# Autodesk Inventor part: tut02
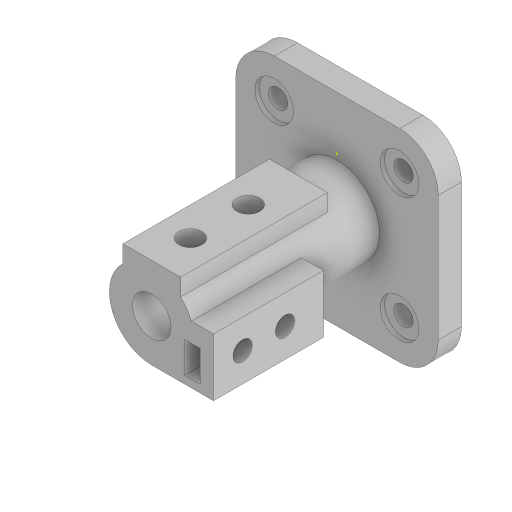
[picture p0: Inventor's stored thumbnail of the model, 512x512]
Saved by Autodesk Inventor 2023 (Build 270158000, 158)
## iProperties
Created: 2015-03
Part Number: tut02
Material: Generic
Document SubType Name: Modeling
Designer: Sandeep
Density: 1 g/cm^3
Appearance: Default
Author: Sandeep
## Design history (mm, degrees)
sketch "Sketch1"
  geometry: L1 (-32.5, -52.5)-(32.5, -52.5); L2 (52.5, -32.5)-(52.5, 32.5); L3 (32.5, 52.5)-(-32.5, 52.5); L4 (-52.5, 32.5)-(-52.5, -32.5); L5 (-52.5, -52.5)-(52.5, 52.5); L6 (52.5, -52.5)-(-52.5, 52.5); A1 r 20 centre (32.5, 32.5) between (52.5, 32.5) and (32.5, 52.5); A2 r 20 centre (32.5, -32.5) between (32.5, -52.5) and (52.5, -32.5); A3 r 20 centre (-32.5, -32.5) between (-52.5, -32.5) and (-32.5, -52.5); A4 r 20 centre (-32.5, 32.5) between (-32.5, 52.5) and (-52.5, 32.5); 1 further point
  constraints: 12 end point, 8 point on circle, 8 point on line, 8 tangent, 4 centre point, 2 equal radius, 2 midpoint, 2 parallel, 1 horizontal, 1 perpendicular
  dimensions: "d0" = 105 distance of L6.start L5.end; "d1" = 105 distance of L5.start L6.start; "d2" = 20 radius of A1; "d3" = 20 radius of A2
extrude "Extrusion1" new body sketch "Sketch1" distance "d4" = 12; taper "d5" = 0 deg
hole "Hole1" diameter "d8" = 10; stored, may be unused: countersink angle "d12" = 90 deg, drill point angle "d14" = 118 deg; dims "d9" = 6, "d10" = 20, "d11" = 2, "d13" = 8, "d15" = 10, "d16" = 10
hole "Hole2" diameter "d19" = 10; stored, may be unused: countersink angle "d23" = 90 deg, drill point angle "d25" = 118 deg; dims "d17" = 10, "d18" = 10, "d20" = 6, "d21" = 20, "d22" = 2, "d24" = 8
hole "Hole3" diameter "d28" = 10; stored, may be unused: countersink angle "d32" = 90 deg, drill point angle "d34" = 118 deg; dims "d26" = 10, "d27" = 10, "d29" = 6, "d30" = 20, "d31" = 2, "d33" = 8
hole "Hole4" diameter "d37" = 10; stored, may be unused: countersink angle "d41" = 90 deg, drill point angle "d43" = 118 deg; dims "d35" = 10, "d36" = 10, "d38" = 6, "d39" = 20, "d40" = 2, "d42" = 8
sketch "Sketch2"
  geometry: C1 r 22 at (0, 0); 1 further point
  constraints: 1 centre point, 1 coincident
  dimensions: "d44" = 44 diameter of C1
extrude "Extrusion2" join sketch "Sketch2" distance "d45" = 96; taper "d46" = 0 deg
sketch "Sketch3"
  geometry: L1 (-15, 16.093)-(-15, 25); L2 (15, 16.093)-(15, 25); L3 (-15, 25)-(15, 25); L4 (0, 0)-(20.619, 0); L5 (0, 6.043)-(0, 0); A1 r 22 centre (0, 0) between (15, 16.093) and (-15, 16.093); 1 further point
  constraints: 10 end point, 3 vertical, 2 horizontal, 2 point on circle, 1 centre point, 4 other
  dimensions: "d48" = 25 distance from line of point (0, 0) L3; "d49" = 30 distance of L1.end L2.end
extrude "Extrusion3" join sketch "Sketch3" distance "d51" = 76; taper "d52" = 0 deg
sketch "Sketch4"
  geometry: L1 (20.494, 8)-(32, 8); L2 (32, 8)-(32, -22); L3 (0, 0)-(37.067, 0); L4 (0, -22)-(32, -22); A1 r 22 centre (0, 0) between (20.494, 8) and (0, -22) reference; A2 r 22 centre (0, 0) between (0, -22) and (20.494, 8); 1 further point
  constraints: 8 end point, 5 point on circle, 2 horizontal, 2 perpendicular, 1 centre point, 1 concentric, 1 tangent
  dimensions: "d53" = 30 distance of L2.end L1.end; "d54" = 32 distance from line of L2 point (0, 0)
extrude "Extrusion4" join sketch "Sketch4" distance "d55" = 57; taper "d56" = 0 deg
sketch "Sketch5"
  geometry: L1 (17, -2)-(25, -2); L2 (25, -2)-(25, -18); L3 (25, -18)-(17, -18); L4 (17, -18)-(17, -2); 1 further point
  constraints: 8 end point, 2 parallel, 1 horizontal, 1 perpendicular
  dimensions: "d57" = 16 distance of L1.end L2.end; "d58" = 2 distance from line of point (0, 0) L1; "d59" = 25 distance from line of point (0, 0) L2; "d60" = 8 distance of L2.end L3.end
extrude "Extrusion5" cut sketch "Sketch5" distance "d61" = 50; taper "d62" = 0 deg
sketch "Sketch6"
  geometry: 1 further point
sketch "Sketch8"
  geometry: 1 further point
hole "Hole10" diameter "d113" = 10; stored, may be unused: countersink angle "d117" = 90 deg, drill point angle "d119" = 118 deg; dims "d111" = 15, "d112" = 15, "d114" = 6, "d115" = 4, "d116" = 2, "d118" = 96
hole "Hole11" diameter "d122" = 10; stored, may be unused: countersink angle "d126" = 90 deg, drill point angle "d128" = 118 deg; dims "d120" = 37, "d121" = 15, "d123" = 6, "d124" = 4, "d125" = 2, "d127" = 96
sketch "Sketch9"
  geometry: C1 r 10 at (0, 0); 1 further point
  constraints: 1 centre point, 1 coincident
  dimensions: "d129" = 20 diameter of C1
extrude "Extrusion7" cut sketch "Sketch9" distance "d130" = 96; taper "d131" = 0 deg
sketch "Sketch10"
  geometry: L1 (15, -0.369)-(15, 146.33); L2 (30, 0)-(30, 76) reference; L3 (0, 0)-(30, 0) reference; C1 r 6 at (15, 20); C2 r 6 at (15, 50); 1 further point
  constraints: 2 centre point, 2 end point, 2 point on line, 1 equal radius, 1 vertical
  dimensions: "d132" = 15 distance between parallel lines of L1 L2; "d133" = 12 diameter of C1; "d134" = 20 distance from line of C1.centre L3; "d135" = 30 distance of C2.centre C1.centre
extrude "Extrusion8" cut sketch "Sketch10" stored distance "d136" = 96; taper "d137" = 0 deg
body "Solid1"
